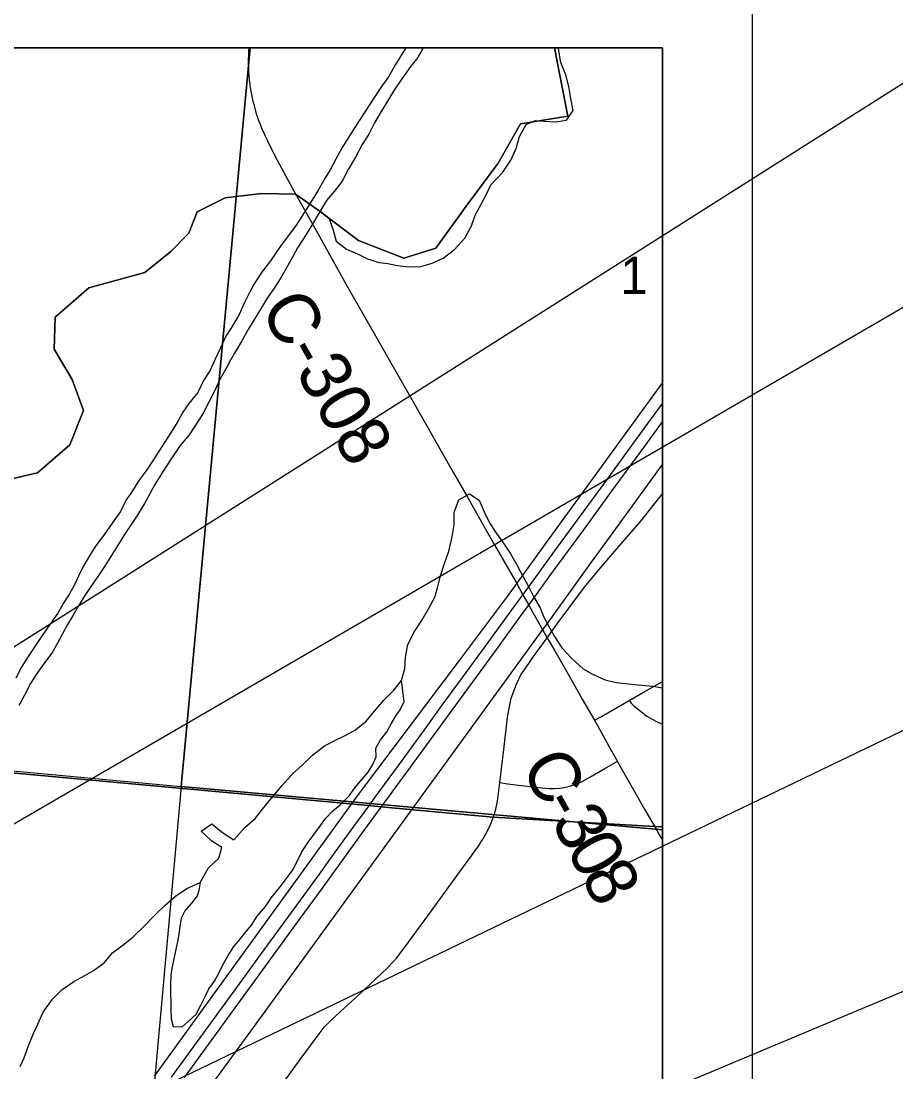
# Model space of a CAD drawing. Extents: x 0 to 34, y 0 to 22.
# Drawn here: x 8.184 to 9.161, y 19.757 to 20.93 of the extents above; entities that cross this region are included whole.
import ezdxf

# ---------------------------------------------------------------- set-up
doc = ezdxf.new("R2010")
doc.units = 0
for name, color, linetype in [('Default', 7, 'Continuous'), ('GM_X_City_Street', 7, 'Continuous'), ('GM_X_County_Road', 7, 'Continuous'), ('GM_X_County_Road_Text', 7, 'Continuous'), ('GM_X_Major_River', 7, 'Continuous'), ('GM_X_Minor_Lake', 7, 'Continuous'), ('GM_X_Minor_River', 7, 'Continuous'), ('GM_X_Rail_Line', 7, 'Continuous'), ('GM_X_Section', 7, 'Continuous'), ('GM_X_Section_Text', 7, 'Continuous'), ('GM_X_Township_Road', 7, 'Continuous'), ('GM_X_US_Route', 7, 'Continuous'), ('SC_Shading1', 7, 'Continuous'), ('SH_Data', 7, 'Continuous'), ('SH_Text', 7, 'Continuous')]:
    doc.layers.add(name, color=color, linetype=linetype)

msp = doc.modelspace()

# ---------------------------------------------------------------- linework, layer by layer
at = {"layer": 'Default'}
for points in [[(8.4399, 20.9), (7.4217, 20.9), (7.3544, 20.1697), (8.363, 20.076)], [(8.9, 20.0275), (8.9, 20.9), (8.4399, 20.9), (8.363, 20.076)], [(8.9, 19.0088), (8.9, 20.0275), (8.363, 20.076), (8.272, 19.073)]]:
    msp.add_lwpolyline(points, close=True, dxfattribs=at)
at = {"layer": 'GM_X_City_Street'}
for points in [[(8.1577, 20.4154), (8.2026, 20.4259), (8.2385, 20.457), (8.2537, 20.4954), (8.2411, 20.5302), (8.221, 20.564), (8.2221, 20.5996), (8.2599, 20.6322), (8.3224, 20.6495), (8.3514, 20.6728), (8.3716, 20.6934), (8.3807, 20.7173), (8.412, 20.7326), (8.453, 20.7374), (8.4906, 20.7369), (8.5154, 20.7192), (8.5606, 20.6852), (8.6115, 20.6654), (8.6472, 20.6766), (8.6809, 20.7235), (8.7168, 20.7713), (8.7416, 20.8152), (8.7944, 20.8239), (8.7795, 20.9), (3.3961, 20.9)], [(8.0393, 20.1035), (8.5721, 20.0545), (8.5859, 20.0532), (8.7108, 20.0415), (8.8912, 20.0313), (8.9, 20.0308), (8.9, 20.9), (8.7795, 20.9), (8.7944, 20.8239), (8.7416, 20.8152), (8.7168, 20.7713), (8.6809, 20.7235), (8.6472, 20.6766), (8.6115, 20.6654), (8.5606, 20.6852), (8.5154, 20.7192), (8.4906, 20.7369), (8.453, 20.7374), (8.412, 20.7326), (8.3807, 20.7173), (8.3716, 20.6934), (8.3514, 20.6728), (8.3224, 20.6495), (8.2599, 20.6322), (8.2221, 20.5996), (8.221, 20.564), (8.2411, 20.5302), (8.2537, 20.4954), (8.2385, 20.457), (8.2026, 20.4259), (8.1577, 20.4154)], [(8.9, 14.1), (8.9, 20.0308), (8.8912, 20.0313), (8.7108, 20.0415), (8.5859, 20.0532), (8.5721, 20.0545), (8.0393, 20.1035)], [(8.7186, 20.0802), (8.727, 20.079), (8.7615, 20.0747), (8.7737, 20.0736), (8.78, 20.0736), (8.7859, 20.0741), (8.7918, 20.0751), (8.7976, 20.0765), (8.8033, 20.0785), (8.8089, 20.0808), (8.819, 20.0862), (8.8351, 20.0955), (8.8486, 20.1033), (8.8497, 20.1039)]]:
    msp.add_lwpolyline(points, dxfattribs=at)
at = {"layer": 'GM_X_County_Road'}
msp.add_line((8.8949, 20.0247), (8.9, 20.016), dxfattribs=at)
for points in [[(8.4383, 20.9), (8.4381, 20.8959), (8.4378, 20.8835), (8.438, 20.8741), (8.4384, 20.8694), (8.4387, 20.8647), (8.4399, 20.8554), (8.4416, 20.8462), (8.4433, 20.8389)], [(8.4433, 20.8389), (8.4438, 20.8371), (8.4463, 20.8281), (8.4493, 20.8192), (8.451, 20.8148), (8.4527, 20.8105), (8.4592, 20.7963), (8.4675, 20.7796), (8.4866, 20.7439), (8.4908, 20.7363)], [(8.4908, 20.7363), (8.5033, 20.714), (8.5171, 20.6897), (8.549, 20.6327), (8.5678, 20.5997), (8.6173, 20.5129), (8.6371, 20.4782), (8.6529, 20.4502), (8.6668, 20.4259), (8.682, 20.3995), (8.6957, 20.3749), (8.7128, 20.3448), (8.7373, 20.3022)], [(8.7186, 20.0802), (8.7233, 20.1203), (8.7271, 20.1532), (8.7313, 20.1746), (8.7369, 20.19), (8.7421, 20.2003), (8.7474, 20.2084), (8.758, 20.2236), (8.7654, 20.2337), (8.7714, 20.2419), (8.7835, 20.2587), (8.7965, 20.2764), (8.8131, 20.2983), (8.8312, 20.3202), (8.8514, 20.3437), (8.8757, 20.3721), (8.8912, 20.3913), (8.9, 20.4026)], [(8.7373, 20.3022), (8.7442, 20.2898), (8.7507, 20.2783), (8.7552, 20.2702), (8.7714, 20.2419), (8.7798, 20.2273)], [(8.7798, 20.2273), (8.7931, 20.2039), (8.7996, 20.1926)], [(8.7996, 20.1926), (8.8105, 20.1734), (8.8241, 20.1497)], [(8.8241, 20.1497), (8.8273, 20.1439), (8.8403, 20.1208), (8.8497, 20.1039)], [(8.8497, 20.1039), (8.8538, 20.0964), (8.88, 20.0506), (8.8867, 20.039), (8.8914, 20.0307), (8.8939, 20.0264), (8.8949, 20.0247)], [(8.7106, 20.04), (8.711, 20.041), (8.7113, 20.0418), (8.7139, 20.0506), (8.7158, 20.0596), (8.7186, 20.0802)], [(8.4783, 19.7471), (8.4945, 19.7698), (8.5167, 19.7998), (8.5226, 19.8072), (8.5291, 19.814), (8.5405, 19.8246), (8.5611, 19.8434), (8.5926, 19.8732), (8.5991, 19.8797), (8.6032, 19.8843), (8.6125, 19.8965), (8.6381, 19.9316), (8.6765, 19.9842), (8.6945, 20.0094), (8.6996, 20.0171), (8.7041, 20.025), (8.7081, 20.0333), (8.7106, 20.04)]]:
    msp.add_lwpolyline(points, dxfattribs=at)
at = {"layer": 'GM_X_Major_River'}
for points in [[(8.6331, 20.9), (8.6327, 20.8993), (8.6271, 20.8892), (8.6193, 20.8795), (8.6083, 20.8646), (8.6, 20.8518), (8.5921, 20.8387), (8.5862, 20.829), (8.5787, 20.8163), (8.5723, 20.8039), (8.5648, 20.7923), (8.5573, 20.7781), (8.5494, 20.7642), (8.5426, 20.7514), (8.5336, 20.7399), (8.525, 20.7298), (8.5183, 20.7186), (8.5108, 20.7059), (8.5025, 20.692), (8.4927, 20.6771), (8.4871, 20.6666), (8.4804, 20.6546), (8.474, 20.6433), (8.4665, 20.6321), (8.4587, 20.6209), (8.4504, 20.6067), (8.4377, 20.5857), (8.4306, 20.5733), (8.4235, 20.5614), (8.4179, 20.5516), (8.4128, 20.5419), (8.406, 20.5299), (8.4, 20.5171), (8.3941, 20.5055), (8.3869, 20.4916), (8.3782, 20.4781), (8.3719, 20.4684), (8.3618, 20.4565), (8.3508, 20.4404), (8.3429, 20.4277), (8.3334, 20.4127), (8.3283, 20.403), (8.3219, 20.3917), (8.3144, 20.3794), (8.3065, 20.367), (8.2998, 20.3569), (8.2931, 20.3461), (8.2845, 20.3326), (8.2774, 20.3214), (8.2699, 20.3102), (8.262, 20.299), (8.2553, 20.2889), (8.2482, 20.2773), (8.2423, 20.2672), (8.236, 20.2567), (8.2249, 20.2357), (8.2185, 20.2248), (8.2091, 20.2125), (8.2009, 20.2009), (8.1949, 20.1908), (8.1878, 20.1769), (8.1818, 20.1664)], [(8.6137, 20.9), (8.6019, 20.8814), (8.5943, 20.8679), (8.5857, 20.856), (8.577, 20.8429), (8.5688, 20.8302), (8.5617, 20.8193), (8.5506, 20.8018), (8.5424, 20.789), (8.5356, 20.7759), (8.5292, 20.7639), (8.5233, 20.7542), (8.5154, 20.7407), (8.5067, 20.7269), (8.5004, 20.7168), (8.4913, 20.7022), (8.4827, 20.6906), (8.4745, 20.6798), (8.4627, 20.6626), (8.4537, 20.651), (8.4443, 20.6368), (8.4391, 20.6271)], [(8.4391, 20.6271), (8.4335, 20.6158), (8.4275, 20.6027), (8.4192, 20.5881), (8.4129, 20.5783), (8.4069, 20.5652), (8.4009, 20.5528), (8.3949, 20.5396), (8.3878, 20.5288), (8.3814, 20.5157), (8.3716, 20.5034), (8.3646, 20.4936), (8.359, 20.4831), (8.3511, 20.47), (8.3409, 20.4547), (8.3318, 20.4401), (8.3247, 20.4293), (8.3157, 20.4173), (8.3086, 20.4057), (8.3015, 20.3956), (8.2951, 20.3829), (8.2857, 20.3698), (8.2767, 20.3564), (8.2673, 20.344), (8.261, 20.3339), (8.2531, 20.3205), (8.2483, 20.3107), (8.2439, 20.3009), (8.2383, 20.2908), (8.232, 20.2811), (8.2253, 20.2691), (8.2162, 20.2568), (8.2064, 20.2422), (8.1997, 20.2321), (8.1922, 20.2209), (8.1851, 20.2096), (8.1784, 20.1969)]]:
    msp.add_lwpolyline(points, dxfattribs=at)
at = {"layer": 'GM_X_Minor_Lake'}
for points in [[(8.384, 19.9686), (8.3824, 19.9599), (8.3809, 19.9538), (8.3744, 19.9455), (8.3668, 19.9373), (8.3629, 19.9289), (8.3613, 19.9198), (8.3601, 19.9111), (8.3586, 19.9028), (8.3566, 19.8926), (8.3542, 19.8816), (8.3523, 19.8733), (8.3515, 19.8653), (8.351, 19.8558), (8.351, 19.8497), (8.3509, 19.844), (8.3512, 19.8361), (8.3512, 19.8266), (8.3518, 19.8167), (8.354, 19.808), (8.3639, 19.8075), (8.3707, 19.8135), (8.3795, 19.8218), (8.3849, 19.832), (8.3891, 19.8407), (8.3937, 19.8502), (8.4002, 19.8585), (8.4048, 19.8675), (8.4098, 19.8777), (8.4152, 19.8872), (8.4217, 19.8974), (8.427, 19.9034), (8.4335, 19.9117), (8.4412, 19.9211), (8.4477, 19.9313), (8.4568, 19.9419), (8.4637, 19.9521), (8.4733, 19.9638), (8.4805, 19.9732), (8.4874, 19.983), (8.4924, 19.9921), (8.497, 20.0023), (8.5039, 20.0128), (8.5112, 20.0226), (8.5177, 20.0313), (8.5241, 20.04), (8.5322, 20.0487), (8.5398, 20.0551), (8.5504, 20.0656), (8.5566, 20.0743), (8.565, 20.0841), (8.5715, 20.092), (8.5768, 20.1003), (8.5803, 20.109), (8.58, 20.1185), (8.5853, 20.1279), (8.5922, 20.137), (8.5972, 20.1457), (8.6022, 20.154), (8.6072, 20.1615), (8.6118, 20.1706), (8.6089, 20.1941)], [(8.4878, 20.0907), (8.4974, 20.0994), (8.5096, 20.111), (8.5229, 20.1212), (8.5343, 20.1272), (8.5445, 20.132), (8.5563, 20.1384), (8.5689, 20.1485), (8.5788, 20.1598), (8.5891, 20.1723), (8.6001, 20.1832), (8.6089, 20.1941)], [(8.384, 19.9686), (8.3932, 19.9852), (8.405, 19.9958), (8.4082, 20.0079), (8.3969, 20.0152), (8.3852, 20.0259), (8.397, 20.0341), (8.409, 20.0246), (8.4215, 20.0165), (8.434, 20.0301), (8.4459, 20.0406), (8.4535, 20.0504), (8.4638, 20.0628), (8.4756, 20.0768), (8.4878, 20.0907)]]:
    msp.add_lwpolyline(points, dxfattribs=at)
at = {"layer": 'GM_X_Minor_River'}
for points in [[(8.5181, 20.7182), (8.5281, 20.7094), (8.5325, 20.6965), (8.5358, 20.6843), (8.5475, 20.6755), (8.5596, 20.6701), (8.5709, 20.6647), (8.5837, 20.6605), (8.5935, 20.6593), (8.6041, 20.6573), (8.6177, 20.6557), (8.6302, 20.6563), (8.6431, 20.66), (8.6552, 20.6656), (8.6678, 20.675), (8.6796, 20.6878), (8.6869, 20.7014), (8.6908, 20.7135), (8.6977, 20.7256), (8.7034, 20.7361), (8.7084, 20.7471), (8.7218, 20.7614), (8.7309, 20.7746), (8.7367, 20.7879), (8.7406, 20.8011), (8.7479, 20.8147), (8.7581, 20.8192), (8.768, 20.8183), (8.7808, 20.8175), (8.7929, 20.8193), (8.8002, 20.8302), (8.7977, 20.8435), (8.7955, 20.8568), (8.7922, 20.8701), (8.7866, 20.8838), (8.7844, 20.8967), (8.7841, 20.9)], [(8.4878, 20.0907), (8.4974, 20.0994), (8.5096, 20.111), (8.5229, 20.1212), (8.5343, 20.1272), (8.5445, 20.132), (8.5563, 20.1384), (8.5689, 20.1485), (8.5788, 20.1598), (8.5891, 20.1723), (8.6001, 20.1832), (8.6089, 20.1941), (8.6124, 20.207), (8.6133, 20.2203), (8.616, 20.2343), (8.6233, 20.249), (8.6318, 20.2618), (8.6387, 20.2743), (8.6459, 20.2871), (8.649, 20.2974), (8.6522, 20.311), (8.6568, 20.3246), (8.6615, 20.3386), (8.6654, 20.3545), (8.6674, 20.3678), (8.6675, 20.3818), (8.6729, 20.3958), (8.6846, 20.4025), (8.6956, 20.3952), (8.7011, 20.3823), (8.7071, 20.3701), (8.7149, 20.3583), (8.7213, 20.3488), (8.7299, 20.3362), (8.7374, 20.3232), (8.7445, 20.3099), (8.7497, 20.3004), (8.756, 20.2878), (8.7635, 20.2752), (8.7672, 20.2657), (8.7728, 20.2551), (8.7795, 20.2432), (8.7877, 20.2307), (8.799, 20.2188), (8.8114, 20.2073), (8.8212, 20.2016), (8.8359, 20.195), (8.8484, 20.1919), (8.8582, 20.1907), (8.8729, 20.1894), (8.8892, 20.1878), (8.9, 20.1861)], [(8.1831, 19.7634), (8.1877, 19.7732), (8.1931, 19.7887), (8.1985, 19.8008), (8.2028, 19.8107), (8.2089, 19.8239), (8.2192, 19.8386), (8.2299, 19.8495), (8.2432, 19.8582), (8.2554, 19.8649), (8.2656, 19.8709), (8.2774, 19.8795), (8.2862, 19.8901), (8.298, 19.8991), (8.3094, 19.9081), (8.3212, 19.9198), (8.3334, 19.9322), (8.3452, 19.9435), (8.3567, 19.9536), (8.3691, 19.9621), (8.384, 19.9686), (8.3932, 19.9852), (8.405, 19.9958), (8.4082, 20.0079), (8.3969, 20.0152), (8.3852, 20.0259), (8.397, 20.0341), (8.409, 20.0246), (8.4215, 20.0165), (8.434, 20.0301), (8.4459, 20.0406), (8.4535, 20.0504), (8.4638, 20.0628), (8.4756, 20.0768), (8.4878, 20.0907)]]:
    msp.add_lwpolyline(points, dxfattribs=at)
at = {"layer": 'GM_X_Rail_Line'}
msp.add_lwpolyline([(7.6723, 18.7457), (7.7577, 18.8632), (7.811, 18.9366), (7.8166, 18.9442), (7.9061, 19.0673), (8.0478, 19.2623), (8.1052, 19.3415), (8.1259, 19.3699), (8.1381, 19.3866), (8.1499, 19.403), (8.3266, 19.6461), (8.4595, 19.8287), (8.7629, 20.246), (8.7734, 20.2604), (8.8197, 20.3248), (8.845, 20.3592), (8.9, 20.435)], dxfattribs=at)
at = {"layer": 'GM_X_Section'}
msp.add_lwpolyline([(8.363, 20.076), (8.272, 19.073), (7.2676, 19.1705), (7.3544, 20.1697)], close=True, dxfattribs=at)
at = {"layer": 'GM_X_Township_Road'}
for points in [[(8.8629, 20.1718), (8.8797, 20.1814), (8.8939, 20.1896)], [(8.8939, 20.1896), (8.8948, 20.19), (8.9, 20.193)], [(8.8241, 20.1497), (8.8318, 20.1541), (8.8557, 20.1677), (8.8629, 20.1718)], [(8.8629, 20.1718), (8.8638, 20.1706), (8.8651, 20.1689), (8.8657, 20.1682), (8.8664, 20.1675), (8.8685, 20.1655), (8.8731, 20.1617), (8.878, 20.158), (8.8827, 20.1545), (8.8879, 20.1512), (8.8932, 20.1483), (8.8988, 20.1458), (8.9, 20.1455)]]:
    msp.add_lwpolyline(points, dxfattribs=at)
at = {"layer": 'GM_X_US_Route'}
msp.add_line((8.7419, 20.2663), (8.7472, 20.2735), dxfattribs=at)
for points in [[(8.3521, 19.7516), (8.4308, 19.8599), (8.4514, 19.8879), (8.4929, 19.945), (8.5171, 19.9781), (8.5349, 20.0027), (8.5556, 20.0312), (8.5723, 20.054), (8.5795, 20.0638), (8.6105, 20.1065), (8.6343, 20.1391), (8.6543, 20.1668), (8.6983, 20.227), (8.7221, 20.2596), (8.7442, 20.2898), (8.7478, 20.2947), (8.7787, 20.3375), (8.8395, 20.42), (8.8795, 20.4754), (8.9, 20.5032)], [(8.7649, 20.2979), (8.7774, 20.315), (8.8122, 20.3622), (8.8432, 20.405), (8.8803, 20.4556), (8.9, 20.4827)], [(8.7472, 20.2735), (8.7507, 20.2783), (8.7649, 20.2979)], [(8.3666, 19.7512), (8.4956, 19.9287), (8.5195, 19.9609), (8.5669, 20.0263), (8.5861, 20.0527), (8.6187, 20.0976), (8.7109, 20.2237), (8.7419, 20.2663)]]:
    msp.add_lwpolyline(points, dxfattribs=at)
at = {"layer": 'SC_Shading1'}
msp.add_lwpolyline([(8.9, 15.7724), (8.9, 20.5265), (8.7731, 20.3523), (8.7472, 20.3163), (8.7268, 20.2878), (8.6719, 20.215), (8.6367, 20.1682), (8.5604, 20.0669), (8.5605, 20.0668), (8.3376, 19.7592), (8.3327, 19.7528)], dxfattribs=at)
at = {"layer": 'SH_Data'}
for p, q in [((9, 21), (9, 14)), ((2.1, 20.9), (8.9, 20.9)), ((8.9, 20.9), (8.9, 14.1))]:
    msp.add_line(p, q, dxfattribs=at)
at = {"layer": 'SH_Text'}
for points in [[(9.2218, 20.8941), (4.458, 17.8745), (9.2218, 20.6417)], [(9.2453, 20.175), (4.4659, 17.8756), (9.2453, 19.8796)]]:
    msp.add_lwpolyline(points, close=True, dxfattribs=at)

# ---------------------------------------------------------------- texts
at = {"layer": 'GM_X_County_Road_Text'}
for s, height, rotation, p in [('C-308', 0.05682, 299.6403, (8.45, 20.6091)), ('C', 0.0568, 299.0531, (8.7409, 20.0981)), ('-', 0.0568, 299.0129, (8.7636, 20.0573)), ('3', 0.0568, 298.8767, (8.7749, 20.0369)), ('0', 0.0568, 298.539, (8.7917, 20.0064)), ('8', 0.0568, 297.5356, (8.8083, 19.9758))]:
    msp.add_text(s, height=height, rotation=rotation, dxfattribs=at).set_placement(p)
at = {"layer": 'GM_X_Section_Text'}
msp.add_text('1', height=0.0419, rotation=0, dxfattribs=at).set_placement((8.8526, 20.6253))

doc.saveas('drawing.dxf')
